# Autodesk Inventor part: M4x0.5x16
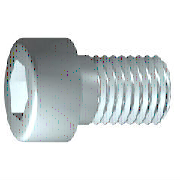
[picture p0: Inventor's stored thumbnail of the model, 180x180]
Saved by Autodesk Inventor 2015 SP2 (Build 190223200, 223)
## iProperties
Created: 2009-02
Part Number: M4x0.5x16
Material: 강, 연강
Description: 6각머리 태핑 나사
Document SubType Name: Modeling
Standard: KS B 1003
Designer: 한국산업디자인학원
Standards Organization: KS
Language: ko-KR
Size Designation: M 4 x 16
Categories: <MemberInstance><Categories><Category DisplayName="조임쇠" InternalName="e4da775c-781d-43d5-af7c-5136215cf5a6" Mnemonic="FSTN"><Category DisplayName="볼트" InternalN
Density: 1 g/cm^3
Appearance: 강철
IsCustomPart: 1
Author: 한국산업디자인학원
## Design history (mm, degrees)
sketch "스케치1"
  geometry: L1 (-1, 0)-(16, 0); L2 (16, 0)-(16, 2); L3 (16, 2)-(1.75, 2); L4 (1.75, 2)-(1.32, 2); L5 (1.32, 2)-(0, 2); L6 (0, 2)-(0, 3.5); L7 (0, 3.5)-(-4, 3.5); L8 (-4, 3.5)-(-4, 1.732); L9 (-4, 1.732)-(-2, 1.732); L10 (-2, 1.732)-(-1, 0); L11 (-8, 0)-(20, 0) reference; L12 (0, -0.7)-(0, 4.2) reference; L13 (1.75, 2)-(0, 2)
  constraints: 22 end point, 6 parallel, 2 collinear, 2 perpendicular, 1 horizontal, 1 point on line
  dimensions: "d1" = 14.25 distance from line of L3.end L2 (= GEL); "d2" = 0.42952 distance of L4.end L3.end (computed from GAL); "d3" = 4 distance between parallel lines of L8 L6 (= KOH); "d4" = 2 distance of L8.end L9.end (= INTI); "d5" = 60 deg angle of L10 L1; "d6" = 4 diameter of L3 L1 (= GD); "d7" = 4 diameter of L5 L1 (= BDM); "d8" = 3.4641 diameter of L9 L1 (= 1.1547 x SW); "d9" = 7 diameter of L7 L1 (= KOD); "d26" = 16 distance between parallel lines of L12 L2 (= NLG)
revolve "본체" sketch "스케치1" stored, may be unused: angle "d10" = 90 deg
sketch "스케치2"
  geometry: L1 (0, -4.9)-(0, 4.9) reference; L2 (-4.9, 0)-(4.9, 0) reference; L3 (1.732, 0)-(0.866, -1.5); L4 (0.866, -1.5)-(-0.866, -1.5); L5 (-0.866, -1.5)-(-1.732, 0); L6 (-1.732, 0)-(-0.866, 1.5); L7 (-0.866, 1.5)-(0.866, 1.5); L8 (0.866, 1.5)-(1.732, 0); 2 further points
  constraints: 12 end point, 1 coincident, 1 horizontal alignment, 1 point on line, 12 other
extrude "슬롯" join sketch "스케치2" stored distance "d11" = 10; taper "d12" = 0 deg
workplane "Work Plane1"
fillet "Fillet2" dims "d30" = 0.1 (= R)
body "Solid1"
fillet "모깎기1" dims "d17" = 0.4 (= RR)
feature "스레드" dims "d13" = 14.25 (= GEL), "d14" = 0
chamfer "모따기1" distance "d15" = 0.42941 (= -0.5 x SPD + 0.5 x GD); stored, may be unused: second distance "d16" = 0.42941 (= GUL), angle "d27" = 45 deg
other parameters: "GD" = 4 (= NND) [user parameter; used in 2 equation terms], "NLG" = 16 [user parameter; used in 1 equation term], "GEL" = 14.25 [user parameter; used in 2 equation terms], "KOD" = 7 [user parameter; used in 1 equation term], "KOH" = 4 [user parameter; used in 1 equation term], "INTI" = 2 [user parameter; used in 1 equation term], "GAL" = 0.42941 (= 0.61345 x PTC) [user parameter; used in 1 equation term], "GUL" = 0.42941 (= 0.61345 x PTC) [user parameter; used in 1 equation term], "BDM" = 4 (= NND) [user parameter; used in 1 equation term], "SW" = 3 [user parameter; used in 2 equation terms], "RR" = 0.4 [user parameter; used in 1 equation term], "SPD" = 3.14117 (= NND - 1.2269 x PTC) [user parameter; used in 1 equation term], "d19" = 0, "d28" = 0, "d29" = 0, "R" = 0.1 [user parameter; used in 1 equation term], "PHH" = 0.2 [user parameter], "GD1" = 3.14117 (= THREADDIA - 1.2269 x PTC) [user parameter], "THREADDIA" = 4 [user parameter; used in 1 equation term], "FAWI" = 45 deg [user parameter], "TPU" = 14.28571 (computed from PTC) [user parameter], "PTC" = 0.7 [user parameter; used in 5 equation terms], "NND" = 4 [user parameter; used in 3 equation terms], "TOA" = 30 deg [user parameter], "E0" = 3.465 (= 1.155 x SW) [user parameter]
